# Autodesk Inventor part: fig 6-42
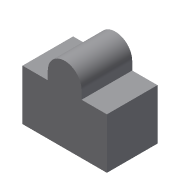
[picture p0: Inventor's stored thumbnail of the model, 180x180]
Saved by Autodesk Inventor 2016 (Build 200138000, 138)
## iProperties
Created: 2005-12
Part Number: fig 6-42
Document SubType Name: Modeling
Designer: CADCIM
Density: 1 g/cm^3
Material: Generic
Appearance: Default
Author: CADCIM
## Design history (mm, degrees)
sketch "Sketch1"
  geometry: L1 (10, 15)-(25, 15); L2 (25, 15)-(25, -15); L3 (25, -15)-(-25, -15); L4 (-25, -15)-(-25, 15); L5 (-25, 15)-(-10, 15); L6 (10, 15)-(10, 30); L7 (10, 30)-(-10, 30); L8 (-10, 30)-(-10, 15)
  constraints: 16 end point, 3 parallel, 3 perpendicular, 2 equal length, 1 collinear, 1 horizontal
  dimensions: "d0" = 50 distance of L2.end L3.end; "d2" = 30 distance of L1.end L2.end; "d3" = 15 distance of L1.start L1.end; "d11" = 15 distance of L7.end L5.end
extrude "Extrusion1" new body sketch "Sketch1" stored distance "d7" = 30; taper "d8" = 0 deg
fillet "Fillet5"
body "Solid1"
